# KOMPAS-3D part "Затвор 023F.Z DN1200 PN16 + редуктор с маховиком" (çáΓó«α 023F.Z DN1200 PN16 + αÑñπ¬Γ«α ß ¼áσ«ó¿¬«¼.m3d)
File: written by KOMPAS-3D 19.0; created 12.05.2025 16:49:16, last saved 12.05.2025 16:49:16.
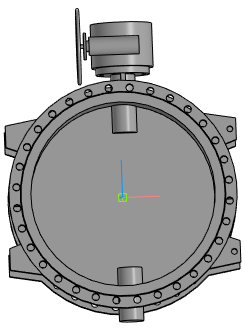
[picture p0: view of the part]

Document properties: Полное имя файла: Затвор 023F.Z DN1200 PN16 + редуктор с маховиком.a3d

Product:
- Part/product: Затвор 023F.Z DN1200 PN16 + редуктор с маховиком
    Масса: 2209.99

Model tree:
1. Операция без истории:1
